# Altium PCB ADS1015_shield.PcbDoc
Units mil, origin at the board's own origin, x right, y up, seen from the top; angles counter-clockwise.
Board outline 688 x 500 mil, 2 copper layers (Top, Bottom), stack 61.811 mil thick; 3 components, 10 nets, 20 pads, 0 vias.
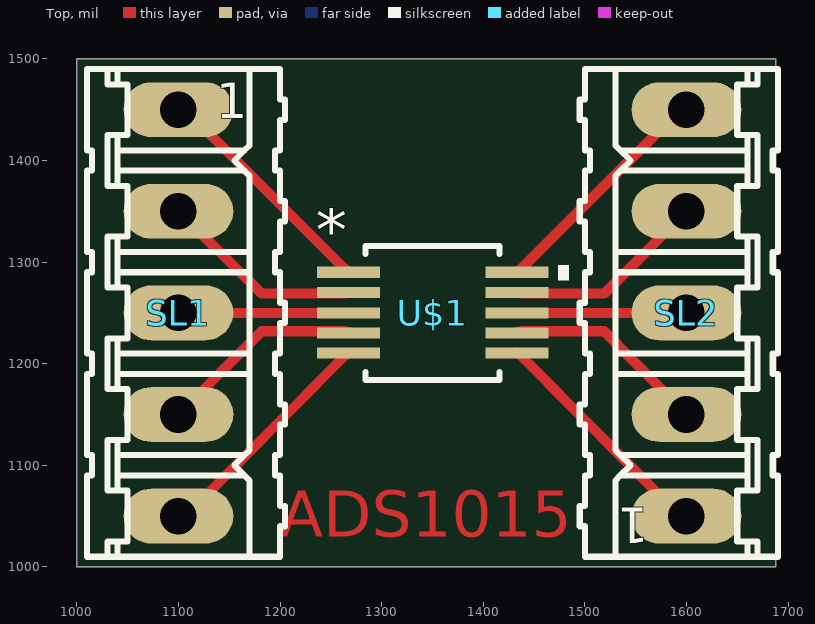
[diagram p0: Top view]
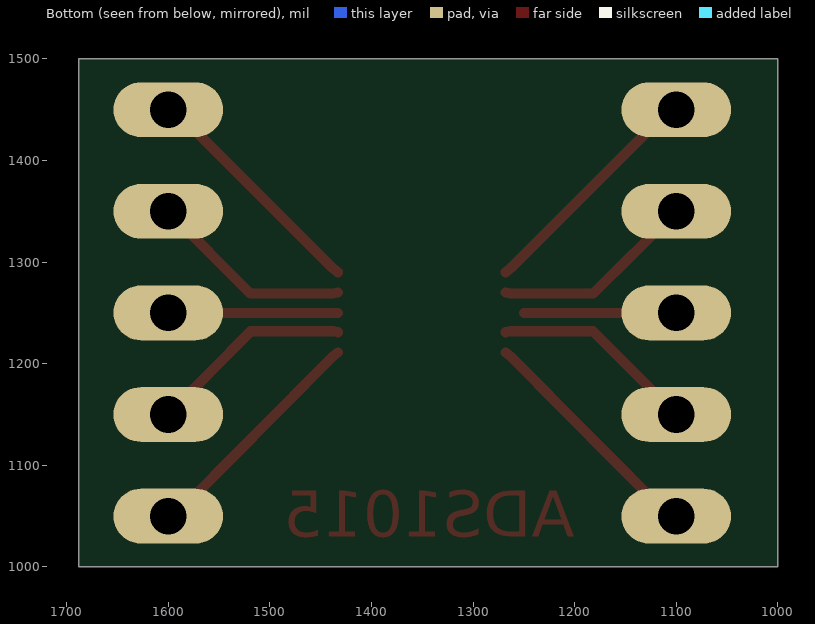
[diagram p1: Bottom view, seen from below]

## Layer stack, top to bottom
Top Solder: solder mask 0.4, Solder Resist, Dk 3.5
Top: signal copper 1.378
Dielectric 1: core 59.0551, FR-4, Dk 4.8
Bottom: signal copper 1.378
Bottom Solder: solder mask 0.4, Solder Resist, Dk 3.5

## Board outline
1000,1000 1688,1000 1688,1500 1000,1500

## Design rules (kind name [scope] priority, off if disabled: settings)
Clearance mdViaVia [IsVia vs IsVia] p1: gap=8
Clearance mdPadVia [IsPad vs IsVia] p2: gap=8
Clearance mdPadPad [IsPad vs IsPad] p3: gap=8
Clearance mdWireVia [(InLayerClass('Signal Layers') AND IsTrack) vs IsVia] p4: gap=8
Clearance mdWirePad [(InLayerClass('Signal Layers') AND IsTrack) vs IsPad] p5: gap=8
Clearance mdWireWire [(InLayerClass('Signal Layers') AND IsTrack) vs (InLayerClass('Signal Layers') AND IsTrack)] p6: gap=8
Clearance [All] p7: gap=8
HoleSize [All] p1: absolutevalues=TRUE maxlimit=100000 minlimit=24 maxpercent=80.000 minpercent=20.000
HoleToHoleClearance [All] p1: gap=8 allowstackedmicrovias=TRUE
PolygonConnect ThermalVias [IsVia] p1: connectstyle=Direct reliefconductorwidth=10 reliefentries=4 polygonreliefangle="90 Angle" airgapwidth=10
PolygonConnect [All] p2: connectstyle=Relief reliefconductorwidth=10 reliefentries=4 polygonreliefangle="90 Angle" airgapwidth=10
RoutingVias [All] p1: holewidth=28 width=50 viastyle="Through Hole" minholewidth=28 minwidth=50 maxholewidth=28 maxwidth=50
SilkToSilkClearance [All] p1 off: silktosilkclearance=10
SilkToSolderMaskClearance [IsPad] p1 off: minsilkscreentomaskgap=10 clearancetoexposedcopper=TRUE
SolderMaskExpansion [All] p1: expansion=4
UnpouredPolygon [All] p1: allowunpoured=FALSE
Width [All] p1: maxlimit=100000 minlimit=10 preferedwidth=10
25 further rules are at their usual default settings.

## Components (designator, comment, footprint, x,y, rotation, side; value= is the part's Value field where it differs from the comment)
SL1 "" 05P 1100,1250 r270 top
SL2 "" 05P 1600,1250 r90 top
U$1 "" DGS10 1350,1250 r0 top

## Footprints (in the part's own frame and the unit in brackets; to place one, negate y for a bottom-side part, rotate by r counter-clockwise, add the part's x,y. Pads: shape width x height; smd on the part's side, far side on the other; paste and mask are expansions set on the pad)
05P [mil] "05P"
  oval 54x108 hole 36: 1(-200,0) 2(-100,0) 3(0,0) 4(100,0) 5(200,0)
  silkscreen extent -240,-90 240,105
DGS10 [mil] "DGS10"
  rect 62x11 smd: 1(-82.5,40) 2(-82.5,20) 3(-82.5,0) 4(-82.5,-19.68) 5(-82.5,-39.37) 6(83,-39.37) 7(83,-19.68) 8(83,0) 9(83,20) 10(83,40)
  silkscreen extent -66,-66 134,66

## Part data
SL1 SL2: library part 05P
U$1: library part DGS10

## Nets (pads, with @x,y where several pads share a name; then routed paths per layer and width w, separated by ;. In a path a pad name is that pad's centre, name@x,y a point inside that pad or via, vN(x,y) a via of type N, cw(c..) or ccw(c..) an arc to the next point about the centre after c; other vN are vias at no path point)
N$1: SL1.1 U$1.1 | length 234
  Top w10: SL1.1 1107,1450 1263,1294 U$1.1@1268,1290
N$2: SL1.2 U$1.2 | length 201.4
  Top w10: SL1.2 1182,1269 1263,1269 U$1.2@1268,1270
N$3: SL1.3 U$1.3 | length 150
  Top w10: SL1.3 U$1.3@1250,1250
N$4: SL1.4 U$1.4 | length 202.1
  Top w10: SL1.4 1182,1232 1263,1232 U$1.4@1268,1231
N$5: SL1.5 U$1.5 | length 234.7
  Top w10: SL1.5 1107,1050 1263,1207 U$1.5@1268,1211
N$6: SL2.1 U$1.6 | length 233.7
  Top w10: U$1.6@1433,1211 1438,1207 1594,1050 SL2.1
N$7: SL2.2 U$1.7 | length 201.4
  Top w10: U$1.7@1433,1231 1438,1232 1519,1232 SL2.2
N$8: SL2.3 U$1.8 | length 167
  Top w10: U$1.8 SL2.3
N$9: SL2.4 U$1.9 | length 200.7
  Top w10: U$1.9 1438,1269 1519,1269 SL2.4
N$10: SL2.5 U$1.10 | length 233
  Top w10: U$1.10 1438,1294 1594,1450 SL2.5

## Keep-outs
Keep-Out Layer:
  the board outline again, w0

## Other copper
Top:
  text "ADS1015" at 1200,1015 h77.5

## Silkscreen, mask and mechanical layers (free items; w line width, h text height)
Dimension:
  the board outline again, w0
Unrouted:
  lines w0: 1250,1250 1268,1250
